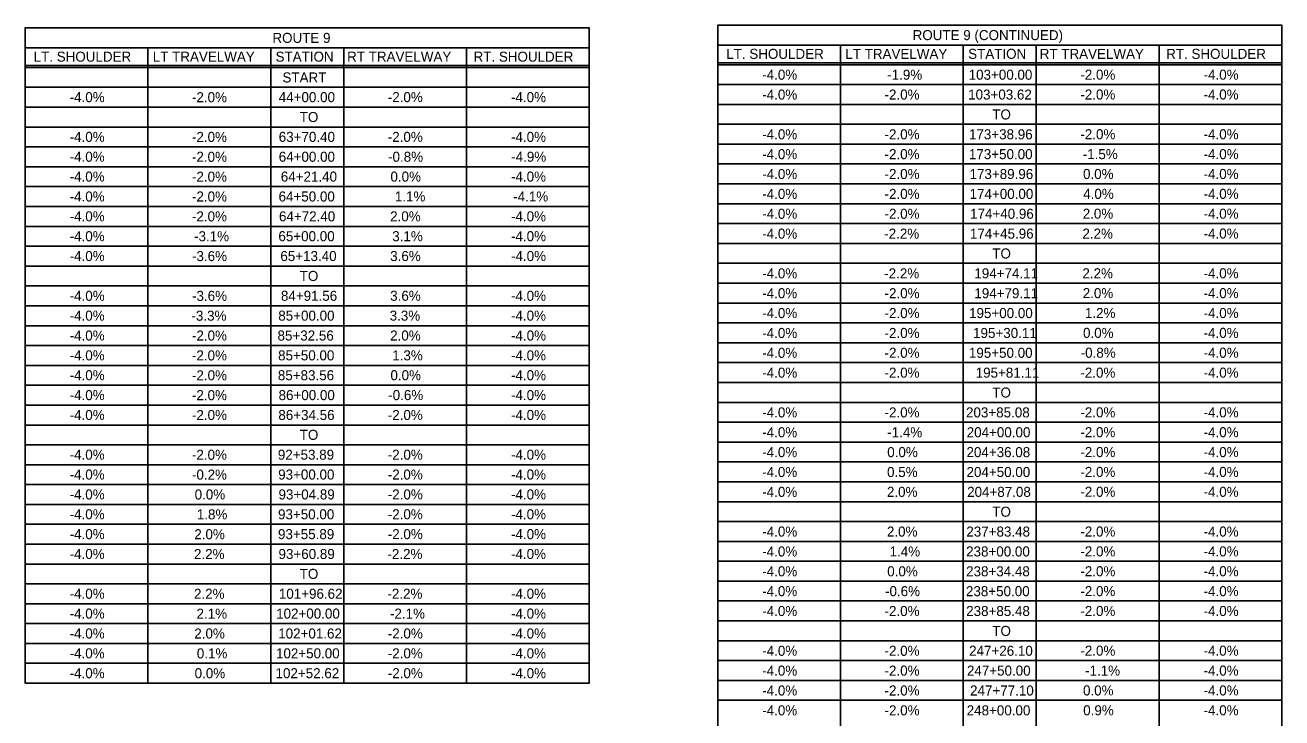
# Model space of a CAD drawing. Extents: x -15319374 to 1762012, y 465773 to 3693661.
# Drawn here: x -15315819.9 to -15315443.6, y 3692272.7 to 3692480 of the extents above; entities that cross this region are included whole.
import ezdxf

# ---------------------------------------------------------------- set-up
doc = ezdxf.new("R2010")
doc.units = 0
doc.layers.add('BORDER', color=7, linetype='Continuous')
doc.layers.add('DIMENSIONS', color=7, linetype='Continuous')

msp = doc.modelspace()

# ---------------------------------------------------------------- linework, layer by layer
at = {"layer": 'BORDER'}
for p, q in [((-15315783.15, 3692473.2), (-15315783.15, 3692283.14)), ((-15315746.39, 3692473.2), (-15315746.39, 3692283.14)), ((-15315724.51, 3692473.2), (-15315724.51, 3692283.14)), ((-15315687.74, 3692473.2), (-15315687.74, 3692283.14)), ((-15315575.73, 3692474.03), (-15315575.73, 3692069.99)), ((-15315538.96, 3692474.03), (-15315538.96, 3692069.99)), ((-15315517.09, 3692474.03), (-15315517.09, 3692069.99)), ((-15315480.32, 3692474.03), (-15315480.32, 3692069.99)), ((-15315819.92, 3692467.91), (-15315650.98, 3692467.91)), ((-15315819.92, 3692467.32), (-15315650.98, 3692467.32)), ((-15315612.5, 3692468.75), (-15315443.55, 3692468.75)), ((-15315612.5, 3692468.15), (-15315443.55, 3692468.15)), ((-15315819.92, 3692461.38), (-15315650.98, 3692461.38)), ((-15315819.92, 3692461.38), (-15315650.98, 3692461.38)), ((-15315819.92, 3692461.38), (-15315650.98, 3692461.38)), ((-15315612.5, 3692462.21), (-15315443.55, 3692462.21)), ((-15315612.5, 3692462.21), (-15315443.55, 3692462.21)), ((-15315612.5, 3692462.21), (-15315443.55, 3692462.21)), ((-15315612.5, 3692456.27), (-15315443.55, 3692456.27)), ((-15315819.92, 3692455.43), (-15315650.98, 3692455.43)), ((-15315819.92, 3692449.49), (-15315650.98, 3692449.49)), ((-15315612.5, 3692450.32), (-15315443.55, 3692450.32)), ((-15315819.92, 3692443.55), (-15315650.98, 3692443.55)), ((-15315612.5, 3692444.38), (-15315443.55, 3692444.38)), ((-15315819.92, 3692437.61), (-15315650.98, 3692437.61)), ((-15315612.5, 3692438.44), (-15315443.55, 3692438.44)), ((-15315819.92, 3692431.66), (-15315650.98, 3692431.66)), ((-15315612.5, 3692432.5), (-15315443.55, 3692432.5)), ((-15315819.92, 3692425.72), (-15315650.98, 3692425.72)), ((-15315612.5, 3692426.55), (-15315443.55, 3692426.55)), ((-15315819.92, 3692419.78), (-15315650.98, 3692419.78)), ((-15315612.5, 3692420.61), (-15315443.55, 3692420.61)), ((-15315612.5, 3692414.67), (-15315443.55, 3692414.67)), ((-15315819.92, 3692413.83), (-15315650.98, 3692413.83)), ((-15315819.92, 3692407.89), (-15315650.98, 3692407.89)), ((-15315612.5, 3692408.73), (-15315443.55, 3692408.73)), ((-15315819.92, 3692401.95), (-15315650.98, 3692401.95)), ((-15315612.5, 3692402.78), (-15315443.55, 3692402.78)), ((-15315819.92, 3692396.01), (-15315650.98, 3692396.01)), ((-15315612.5, 3692396.84), (-15315443.55, 3692396.84)), ((-15315819.92, 3692390.06), (-15315650.98, 3692390.06)), ((-15315612.5, 3692390.9), (-15315443.55, 3692390.9)), ((-15315612.5, 3692384.95), (-15315443.55, 3692384.95)), ((-15315819.92, 3692384.12), (-15315650.98, 3692384.12)), ((-15315819.92, 3692378.18), (-15315650.98, 3692378.18)), ((-15315612.5, 3692379.01), (-15315443.55, 3692379.01)), ((-15315612.5, 3692373.07), (-15315443.55, 3692373.07)), ((-15315819.92, 3692372.24), (-15315650.98, 3692372.24)), ((-15315819.92, 3692366.29), (-15315650.98, 3692366.29)), ((-15315612.5, 3692367.13), (-15315443.55, 3692367.13)), ((-15315819.92, 3692360.35), (-15315650.98, 3692360.35)), ((-15315612.5, 3692361.18), (-15315443.55, 3692361.18)), ((-15315819.92, 3692354.41), (-15315650.98, 3692354.41)), ((-15315612.5, 3692355.24), (-15315443.55, 3692355.24)), ((-15315819.92, 3692348.46), (-15315650.98, 3692348.46)), ((-15315612.5, 3692349.3), (-15315443.55, 3692349.3)), ((-15315612.5, 3692343.36), (-15315443.55, 3692343.36)), ((-15315819.92, 3692342.52), (-15315650.98, 3692342.52)), ((-15315819.92, 3692336.58), (-15315650.98, 3692336.58)), ((-15315612.5, 3692337.41), (-15315443.55, 3692337.41)), ((-15315819.92, 3692330.64), (-15315650.98, 3692330.64)), ((-15315612.5, 3692331.47), (-15315443.55, 3692331.47)), ((-15315819.92, 3692324.69), (-15315650.98, 3692324.69)), ((-15315612.5, 3692325.53), (-15315443.55, 3692325.53)), ((-15315819.92, 3692318.75), (-15315650.98, 3692318.75)), ((-15315612.5, 3692319.59), (-15315443.55, 3692319.59)), ((-15315819.92, 3692312.81), (-15315650.98, 3692312.81)), ((-15315612.5, 3692313.64), (-15315443.55, 3692313.64)), ((-15315819.92, 3692306.87), (-15315650.98, 3692306.87)), ((-15315612.5, 3692307.7), (-15315443.55, 3692307.7)), ((-15315612.5, 3692301.76), (-15315443.55, 3692301.76)), ((-15315819.92, 3692300.92), (-15315650.98, 3692300.92)), ((-15315819.92, 3692294.98), (-15315650.98, 3692294.98)), ((-15315612.5, 3692295.81), (-15315443.55, 3692295.81)), ((-15315819.92, 3692289.05), (-15315650.98, 3692289.05)), ((-15315612.5, 3692289.87), (-15315443.55, 3692289.87)), ((-15315612.5, 3692283.93), (-15315443.55, 3692283.93)), ((-15315612.5, 3692277.99), (-15315443.55, 3692277.99))]:
    msp.add_line(p, q, dxfattribs=at)
for points in [[(-15315819.92, 3692473.2), (-15315819.92, 3692479.14), (-15315650.98, 3692479.14), (-15315650.98, 3692473.2)], [(-15315612.5, 3692474.03), (-15315612.5, 3692479.97), (-15315443.55, 3692479.97), (-15315443.55, 3692474.03)]]:
    msp.add_lwpolyline(points, dxfattribs=at)
for points in [[(-15315819.92, 3692473.2), (-15315650.98, 3692473.2), (-15315650.98, 3692283.14), (-15315819.92, 3692283.14)], [(-15315612.5, 3692474.03), (-15315443.55, 3692474.03), (-15315443.55, 3692069.99), (-15315612.5, 3692069.99)]]:
    msp.add_lwpolyline(points, close=True, dxfattribs=at)

# ---------------------------------------------------------------- texts
at = {"layer": 'DIMENSIONS'}
for s, p in [('ROUTE 9 (CONTINUED)', (-15315554.12, 3692475.5)), ('ROUTE 9', (-15315745.86, 3692474.67)), ('LT. SHOULDER', (-15315817.37, 3692469.05)), ('LT TRAVELWAY', (-15315781.7, 3692469.05)), ('STATION', (-15315744.92, 3692469.05)), ('RT TRAVELWAY', (-15315723.49, 3692469.05)), ('RT. SHOULDER', (-15315685.62, 3692469.05)), ('LT. SHOULDER', (-15315609.95, 3692469.89)), ('LT TRAVELWAY', (-15315574.28, 3692469.89)), ('STATION', (-15315537.5, 3692469.89)), ('RT TRAVELWAY', (-15315516.07, 3692469.89)), ('RT. SHOULDER', (-15315478.2, 3692469.89)), ('START', (-15315742.85, 3692462.83)), ('-4.0%', (-15315599.17, 3692463.65)), ('-1.9%', (-15315561.74, 3692463.65)), ('103+00.00', (-15315537.35, 3692463.65)), ('-2.0%', (-15315503.9, 3692463.66)), ('-4.0%', (-15315466.99, 3692463.66)), ('-4.0%', (-15315806.59, 3692456.94)), ('-2.0%', (-15315769.96, 3692456.92)), ('44+00.00', (-15315743.97, 3692456.94)), ('-2.0%', (-15315711.32, 3692456.94)), ('-4.0%', (-15315674.41, 3692456.94)), ('-4.0%', (-15315599.17, 3692457.71)), ('-2.0%', (-15315562.54, 3692457.71)), ('103+03.62', (-15315537.51, 3692457.71)), ('-2.0%', (-15315503.9, 3692457.72)), ('-4.0%', (-15315466.99, 3692457.72)), ('TO', (-15315737.69, 3692450.99)), ('TO', (-15315530.27, 3692451.76)), ('-4.0%', (-15315599.17, 3692445.82)), ('-2.0%', (-15315562.54, 3692445.82)), ('173+38.96', (-15315537.26, 3692445.82)), ('-2.0%', (-15315503.9, 3692445.84)), ('-4.0%', (-15315466.99, 3692445.84)), ('-4.0%', (-15315806.59, 3692445.05)), ('-2.0%', (-15315769.96, 3692445.04)), ('63+70.40', (-15315743.97, 3692445.05)), ('-2.0%', (-15315711.32, 3692445.05)), ('-4.0%', (-15315674.41, 3692445.05)), ('-4.0%', (-15315806.59, 3692439.11)), ('-2.0%', (-15315769.96, 3692439.09)), ('64+00.00', (-15315743.97, 3692439.11)), ('-0.8%', (-15315711.23, 3692439.11)), ('-4.9%', (-15315674.36, 3692439.11)), ('-4.0%', (-15315599.17, 3692439.88)), ('-2.0%', (-15315562.54, 3692439.88)), ('173+50.00', (-15315537.28, 3692439.88)), ('-1.5%', (-15315503.19, 3692439.89)), ('-4.0%', (-15315466.99, 3692439.89)), ('-4.0%', (-15315599.17, 3692433.94)), ('-2.0%', (-15315562.54, 3692433.94)), ('173+89.96', (-15315537.09, 3692433.94)), ('0.0%', (-15315503.1, 3692433.95)), ('-4.0%', (-15315466.99, 3692433.95)), ('-4.0%', (-15315806.59, 3692433.17)), ('-2.0%', (-15315769.96, 3692433.15)), ('64+21.40', (-15315743.36, 3692433.17)), ('0.0%', (-15315710.52, 3692433.17)), ('-4.0%', (-15315674.41, 3692433.17)), ('-4.0%', (-15315806.59, 3692427.22)), ('-2.0%', (-15315769.96, 3692427.21)), ('64+50.00', (-15315744.02, 3692427.22)), ('1.1%', (-15315709.2, 3692427.22)), ('-4.1%', (-15315673.75, 3692427.22)), ('-4.0%', (-15315599.17, 3692427.99)), ('-2.0%', (-15315562.54, 3692427.99)), ('174+00.00', (-15315537.07, 3692427.99)), ('4.0%', (-15315503.05, 3692428.01)), ('-4.0%', (-15315466.99, 3692428.01)), ('-4.0%', (-15315806.59, 3692421.28)), ('-2.0%', (-15315769.96, 3692421.26)), ('64+72.40', (-15315743.9, 3692421.28)), ('2.0%', (-15315710.61, 3692421.28)), ('-4.0%', (-15315674.41, 3692421.28)), ('-4.0%', (-15315599.17, 3692422.05)), ('-2.0%', (-15315562.54, 3692422.05)), ('174+40.96', (-15315536.93, 3692422.05)), ('2.0%', (-15315503.19, 3692422.07)), ('-4.0%', (-15315466.99, 3692422.07)), ('-4.0%', (-15315806.59, 3692415.34)), ('-3.1%', (-15315769.33, 3692415.32)), ('65+00.00', (-15315744.07, 3692415.34)), ('3.1%', (-15315709.98, 3692415.34)), ('-4.0%', (-15315674.41, 3692415.34)), ('-4.0%', (-15315599.17, 3692416.11)), ('-2.2%', (-15315562.64, 3692416.11)), ('174+45.96', (-15315536.97, 3692416.11)), ('2.2%', (-15315503.29, 3692416.12)), ('-4.0%', (-15315466.99, 3692416.12)), ('-4.0%', (-15315806.59, 3692409.4)), ('-3.6%', (-15315769.94, 3692409.38)), ('65+13.40', (-15315743.48, 3692409.4)), ('3.6%', (-15315710.59, 3692409.4)), ('-4.0%', (-15315674.41, 3692409.4)), ('TO', (-15315530.27, 3692410.16)), ('-4.0%', (-15315599.17, 3692404.22)), ('-2.2%', (-15315562.64, 3692404.22)), ('194+74.11', (-15315535.65, 3692404.22)), ('2.2%', (-15315503.29, 3692404.24)), ('-4.0%', (-15315466.99, 3692404.24)), ('TO', (-15315737.69, 3692403.45)), ('-4.0%', (-15315806.59, 3692397.51)), ('-3.6%', (-15315769.94, 3692397.49)), ('84+91.56', (-15315743.31, 3692397.51)), ('3.6%', (-15315710.59, 3692397.51)), ('-4.0%', (-15315674.41, 3692397.51)), ('-4.0%', (-15315599.17, 3692398.28)), ('-2.0%', (-15315562.54, 3692398.28)), ('194+79.11', (-15315535.65, 3692398.28)), ('2.0%', (-15315503.19, 3692398.3)), ('-4.0%', (-15315466.99, 3692398.3)), ('-4.0%', (-15315806.59, 3692391.57)), ('-3.3%', (-15315770.11, 3692391.55)), ('85+00.00', (-15315744.11, 3692391.57)), ('3.3%', (-15315710.75, 3692391.57)), ('-4.0%', (-15315674.41, 3692391.57)), ('-4.0%', (-15315599.17, 3692392.34)), ('-2.0%', (-15315562.54, 3692392.34)), ('195+00.00', (-15315537.23, 3692392.34)), ('1.2%', (-15315502.53, 3692392.35)), ('-4.0%', (-15315466.99, 3692392.35)), ('-4.0%', (-15315806.59, 3692385.62)), ('-2.0%', (-15315769.96, 3692385.61)), ('85+32.56', (-15315744.33, 3692385.62)), ('2.0%', (-15315710.61, 3692385.62)), ('-4.0%', (-15315674.41, 3692385.62)), ('-4.0%', (-15315599.17, 3692386.39)), ('-2.0%', (-15315562.54, 3692386.39)), ('195+30.11', (-15315536.03, 3692386.39)), ('0.0%', (-15315503.1, 3692386.41)), ('-4.0%', (-15315466.99, 3692386.41)), ('-4.0%', (-15315806.59, 3692379.68)), ('-2.0%', (-15315769.96, 3692379.67)), ('85+50.00', (-15315744.16, 3692379.68)), ('1.3%', (-15315709.98, 3692379.68)), ('-4.0%', (-15315674.41, 3692379.68)), ('-4.0%', (-15315599.17, 3692380.45)), ('-2.0%', (-15315562.54, 3692380.45)), ('195+50.00', (-15315537.28, 3692380.45)), ('-0.8%', (-15315503.8, 3692380.47)), ('-4.0%', (-15315466.99, 3692380.47)), ('-4.0%', (-15315806.59, 3692373.74)), ('-2.0%', (-15315769.96, 3692373.72)), ('85+83.56', (-15315744.23, 3692373.74)), ('0.0%', (-15315710.52, 3692373.74)), ('-4.0%', (-15315674.41, 3692373.74)), ('-4.0%', (-15315599.17, 3692374.51)), ('-2.0%', (-15315562.54, 3692374.51)), ('195+81.11', (-15315535.25, 3692374.51)), ('-2.0%', (-15315503.9, 3692374.52)), ('-4.0%', (-15315466.99, 3692374.52)), ('-4.0%', (-15315806.59, 3692367.8)), ('-2.0%', (-15315769.96, 3692367.78)), ('86+00.00', (-15315744.02, 3692367.8)), ('-0.6%', (-15315711.18, 3692367.8)), ('-4.0%', (-15315674.41, 3692367.8)), ('TO', (-15315530.27, 3692368.57)), ('-4.0%', (-15315599.17, 3692362.62)), ('-2.0%', (-15315562.54, 3692362.62)), ('203+85.08', (-15315538.14, 3692362.62)), ('-2.0%', (-15315503.9, 3692362.64)), ('-4.0%', (-15315466.99, 3692362.64)), ('-4.0%', (-15315806.59, 3692361.85)), ('-2.0%', (-15315769.96, 3692361.84)), ('86+34.56', (-15315744.09, 3692361.85)), ('-2.0%', (-15315711.32, 3692361.85)), ('-4.0%', (-15315674.41, 3692361.85)), ('TO', (-15315737.69, 3692355.91)), ('-4.0%', (-15315599.17, 3692356.68)), ('-1.4%', (-15315561.74, 3692356.68)), ('204+00.00', (-15315537.94, 3692356.68)), ('-2.0%', (-15315503.9, 3692356.7)), ('-4.0%', (-15315466.99, 3692356.7)), ('-4.0%', (-15315806.59, 3692349.97)), ('-2.0%', (-15315769.96, 3692349.95)), ('92+53.89', (-15315744.23, 3692349.97)), ('-2.0%', (-15315711.32, 3692349.97)), ('-4.0%', (-15315674.41, 3692349.97)), ('-4.0%', (-15315599.17, 3692350.74)), ('0.0%', (-15315561.74, 3692350.74)), ('204+36.08', (-15315538, 3692350.74)), ('-2.0%', (-15315503.9, 3692350.75)), ('-4.0%', (-15315466.99, 3692350.75)), ('-4.0%', (-15315806.59, 3692344.03)), ('-0.2%', (-15315769.96, 3692344.01)), ('93+00.00', (-15315744.14, 3692344.03)), ('-2.0%', (-15315711.32, 3692344.03)), ('-4.0%', (-15315674.41, 3692344.03)), ('-4.0%', (-15315599.17, 3692344.79)), ('0.5%', (-15315561.79, 3692344.79)), ('204+50.00', (-15315537.99, 3692344.79)), ('-2.0%', (-15315503.9, 3692344.81)), ('-4.0%', (-15315466.99, 3692344.81)), ('-4.0%', (-15315806.59, 3692338.08)), ('0.0%', (-15315769.16, 3692338.07)), ('93+04.89', (-15315744.04, 3692338.08)), ('-2.0%', (-15315711.32, 3692338.08)), ('-4.0%', (-15315674.41, 3692338.08)), ('-4.0%', (-15315599.17, 3692338.85)), ('2.0%', (-15315561.83, 3692338.85)), ('204+87.08', (-15315537.81, 3692338.85)), ('-2.0%', (-15315503.9, 3692338.87)), ('-4.0%', (-15315466.99, 3692338.87)), ('TO', (-15315530.27, 3692332.91)), ('-4.0%', (-15315806.59, 3692332.14)), ('1.8%', (-15315768.5, 3692332.12)), ('93+50.00', (-15315744.18, 3692332.14)), ('-2.0%', (-15315711.32, 3692332.14)), ('-4.0%', (-15315674.41, 3692332.14)), ('-4.0%', (-15315806.59, 3692326.2)), ('2.0%', (-15315769.26, 3692326.18)), ('93+55.89', (-15315744.19, 3692326.2)), ('-2.0%', (-15315711.32, 3692326.2)), ('-4.0%', (-15315674.41, 3692326.2)), ('-4.0%', (-15315599.17, 3692326.97)), ('2.0%', (-15315561.83, 3692326.97)), ('237+83.48', (-15315538.05, 3692326.97)), ('-2.0%', (-15315503.9, 3692326.98)), ('-4.0%', (-15315466.99, 3692326.98)), ('-4.0%', (-15315599.17, 3692321.02)), ('1.4%', (-15315561.03, 3692321.02)), ('238+00.00', (-15315538.11, 3692321.02)), ('-2.0%', (-15315503.9, 3692321.04)), ('-4.0%', (-15315466.99, 3692321.04)), ('-4.0%', (-15315806.59, 3692320.26)), ('2.2%', (-15315769.35, 3692320.24)), ('93+60.89', (-15315744.04, 3692320.26)), ('-2.2%', (-15315711.42, 3692320.26)), ('-4.0%', (-15315674.41, 3692320.26)), ('TO', (-15315737.69, 3692314.31)), ('-4.0%', (-15315599.17, 3692315.08)), ('0.0%', (-15315561.74, 3692315.08)), ('238+34.48', (-15315538.12, 3692315.08)), ('-2.0%', (-15315503.9, 3692315.1)), ('-4.0%', (-15315466.99, 3692315.1)), ('-4.0%', (-15315806.59, 3692308.37)), ('2.2%', (-15315769.35, 3692308.35)), ('101+96.62', (-15315743.94, 3692308.37)), ('-2.2%', (-15315711.42, 3692308.37)), ('-4.0%', (-15315674.41, 3692308.37)), ('-4.0%', (-15315599.17, 3692309.14)), ('-0.6%', (-15315562.4, 3692309.14)), ('238+50.00', (-15315538.16, 3692309.14)), ('-2.0%', (-15315503.9, 3692309.15)), ('-4.0%', (-15315466.99, 3692309.15)), ('-4.0%', (-15315806.59, 3692302.43)), ('2.1%', (-15315768.59, 3692302.41)), ('102+00.00', (-15315744.75, 3692302.43)), ('-2.1%', (-15315710.66, 3692302.43)), ('-4.0%', (-15315674.41, 3692302.43)), ('-4.0%', (-15315599.17, 3692303.2)), ('-2.0%', (-15315562.54, 3692303.2)), ('238+85.48', (-15315538.1, 3692303.2)), ('-2.0%', (-15315503.9, 3692303.21)), ('-4.0%', (-15315466.99, 3692303.21)), ('-4.0%', (-15315806.59, 3692296.48)), ('2.0%', (-15315769.26, 3692296.47)), ('102+01.62', (-15315744.13, 3692296.48)), ('-2.0%', (-15315711.32, 3692296.48)), ('-4.0%', (-15315674.41, 3692296.48)), ('TO', (-15315530.27, 3692297.25)), ('-4.0%', (-15315599.17, 3692291.31)), ('-2.0%', (-15315562.54, 3692291.31)), ('247+26.10', (-15315537.21, 3692291.31)), ('-2.0%', (-15315503.9, 3692291.33)), ('-4.0%', (-15315466.99, 3692291.33)), ('-4.0%', (-15315806.59, 3692290.54)), ('0.1%', (-15315768.5, 3692290.53)), ('102+50.00', (-15315744.8, 3692290.54)), ('-2.0%', (-15315711.32, 3692290.54)), ('-4.0%', (-15315674.41, 3692290.54)), ('-4.0%', (-15315806.59, 3692284.6)), ('0.0%', (-15315769.16, 3692284.58)), ('102+52.62', (-15315744.93, 3692284.6)), ('-2.0%', (-15315711.32, 3692284.6)), ('-4.0%', (-15315674.41, 3692284.6)), ('-4.0%', (-15315599.17, 3692285.37)), ('-2.0%', (-15315562.54, 3692285.37)), ('247+50.00', (-15315537.87, 3692285.37)), ('-1.1%', (-15315502.48, 3692285.38)), ('-4.0%', (-15315466.99, 3692285.38)), ('-4.0%', (-15315599.17, 3692279.42)), ('-2.0%', (-15315562.54, 3692279.42)), ('247+77.10', (-15315536.93, 3692279.42)), ('0.0%', (-15315503.1, 3692279.44)), ('-4.0%', (-15315466.99, 3692279.44)), ('-4.0%', (-15315599.17, 3692273.48)), ('-2.0%', (-15315562.54, 3692273.48)), ('248+00.00', (-15315537.94, 3692273.48)), ('0.9%', (-15315503.05, 3692273.5)), ('-4.0%', (-15315466.99, 3692273.5))]:
    msp.add_text(s, height=3, dxfattribs=at).set_placement(p)

doc.saveas('drawing.dxf')
